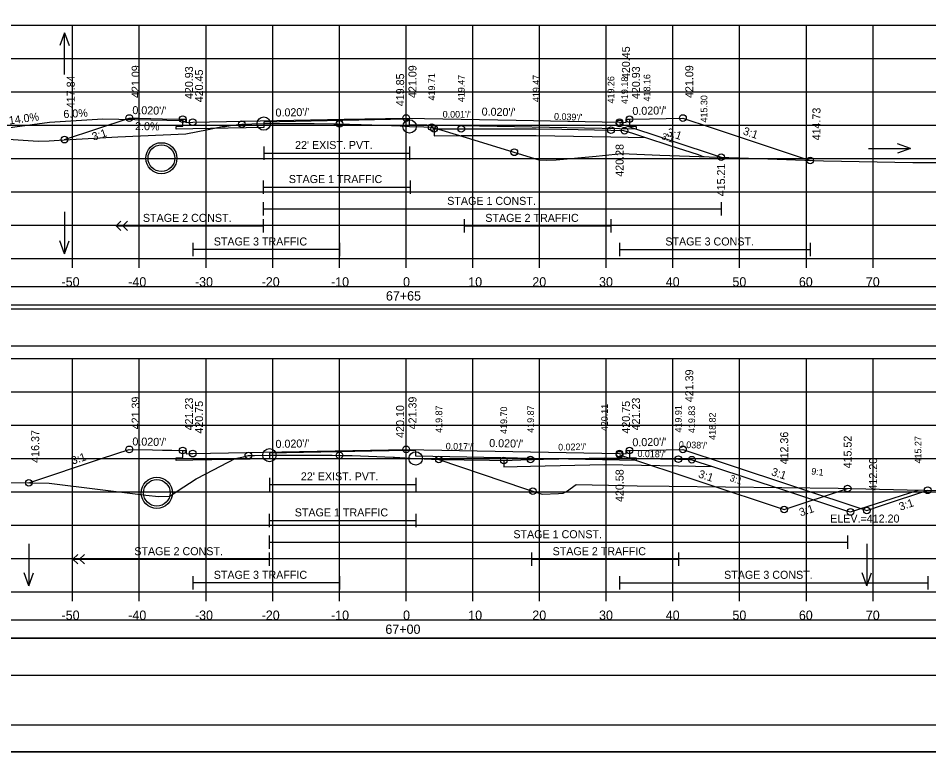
# Model space of a CAD drawing. Extents: x 1371057 to 1372761, y 380005 to 390517.
# Drawn here: x 1371502.7 to 1371639.2, y 385765.2 to 385875.2 of the extents above; entities that cross this region are included whole.
import ezdxf

# ---------------------------------------------------------------- set-up
doc = ezdxf.new("R2010")
doc.units = 0
for name, color, linetype in [('R_Alt Surface', 7, 'Continuous'), ('R_Axis', 7, 'Continuous'), ('R_Axis Annot', 7, 'Continuous'), ('R_Border', 7, 'Continuous'), ('R_Detour', 7, 'Continuous'), ('R_Draft', 7, 'Continuous'), ('R_Drive', 7, 'Continuous'), ('R_Exist Surface', 7, 'Continuous'), ('R_Fin Surface', 7, 'Continuous'), ('R_Fin Surface Annot', 7, 'Continuous'), ('R_Grid', 7, 'Continuous'), ('R_No Plot', 7, 'Continuous'), ('R_Striping', 7, 'Continuous'), ('R_Water', 7, 'Continuous'), ('R_Water Annot', 7, 'Continuous'), ('R_Xsect Elev', 7, 'Continuous'), ('R_Xsect Slope', 7, 'Continuous')]:
    doc.layers.add(name, color=color, linetype=linetype)

msp = doc.modelspace()

# ---------------------------------------------------------------- linework, layer by layer
at = {"layer": 'R_Alt Surface'}
for points in [[(1371594.37, 385860.11), (1371594.37, 385859.03), (1371595.37, 385859.01), (1371595.37, 385858.58), (1371592.87, 385858.63), (1371561.4, 385859.26), (1371561.39, 385860.09), (1371560.87, 385860.1), (1371539.53, 385859.67), (1371539.52, 385858.84), (1371528.87, 385858.63), (1371526.37, 385858.58), (1371526.37, 385859.01), (1371527.37, 385859.03), (1371527.37, 385860.11)], [(1371594.37, 385860.11), (1371594.37, 385859.03), (1371595.37, 385859.01), (1371595.37, 385858.58), (1371592.87, 385858.63), (1371561.4, 385859.26), (1371561.39, 385860.09), (1371560.87, 385860.1), (1371539.53, 385859.67), (1371539.52, 385858.84), (1371528.87, 385858.63), (1371526.37, 385858.58), (1371526.37, 385859.01), (1371527.37, 385859.03), (1371527.37, 385860.11)], [(1371539.53, 385856.02), (1371539.53, 385854.02)], [(1371561.39, 385856.02), (1371561.39, 385854.02)], [(1371539.53, 385855.02), (1371561.39, 385855.02)], [(1371594.37, 385810.41), (1371594.37, 385809.33), (1371595.37, 385809.31), (1371595.37, 385808.88), (1371592.87, 385808.93), (1371562.3, 385809.54), (1371562.3, 385810.37), (1371560.87, 385810.4), (1371540.38, 385809.99), (1371540.38, 385809.16), (1371528.87, 385808.93), (1371526.37, 385808.88), (1371526.37, 385809.31), (1371527.37, 385809.33), (1371527.37, 385810.41)], [(1371594.37, 385810.41), (1371594.37, 385809.33), (1371595.37, 385809.31), (1371595.37, 385808.88), (1371592.87, 385808.93), (1371562.3, 385809.54), (1371562.3, 385810.37), (1371560.87, 385810.4), (1371540.38, 385809.99), (1371540.38, 385809.16), (1371528.87, 385808.93), (1371526.37, 385808.88), (1371526.37, 385809.31), (1371527.37, 385809.33), (1371527.37, 385810.41)], [(1371540.38, 385806.32), (1371540.38, 385804.32)], [(1371562.3, 385806.32), (1371562.3, 385804.32)], [(1371540.38, 385805.32), (1371562.3, 385805.32)]]:
    msp.add_lwpolyline(points, dxfattribs=at)
at = {"layer": 'R_Axis'}
for p, q in [((1371410.87, 385839.19), (1371710.87, 385839.19)), ((1371510.87, 385837.79), (1371510.87, 385839.19)), ((1371520.87, 385837.79), (1371520.87, 385839.19)), ((1371530.87, 385837.79), (1371530.87, 385839.19)), ((1371540.87, 385837.79), (1371540.87, 385839.19)), ((1371550.87, 385837.79), (1371550.87, 385839.19)), ((1371560.87, 385837.79), (1371560.87, 385839.19)), ((1371570.87, 385837.79), (1371570.87, 385839.19)), ((1371580.87, 385837.79), (1371580.87, 385839.19)), ((1371590.87, 385837.79), (1371590.87, 385839.19)), ((1371600.87, 385837.79), (1371600.87, 385839.19)), ((1371610.87, 385837.79), (1371610.87, 385839.19)), ((1371620.87, 385837.79), (1371620.87, 385839.19)), ((1371630.87, 385837.79), (1371630.87, 385839.19)), ((1371410.87, 385789.19), (1371710.87, 385789.19)), ((1371510.87, 385787.79), (1371510.87, 385789.19)), ((1371520.87, 385787.79), (1371520.87, 385789.19)), ((1371530.87, 385787.79), (1371530.87, 385789.19)), ((1371540.87, 385787.79), (1371540.87, 385789.19)), ((1371550.87, 385787.79), (1371550.87, 385789.19)), ((1371560.87, 385787.79), (1371560.87, 385789.19)), ((1371570.87, 385787.79), (1371570.87, 385789.19)), ((1371580.87, 385787.79), (1371580.87, 385789.19)), ((1371590.87, 385787.79), (1371590.87, 385789.19)), ((1371600.87, 385787.79), (1371600.87, 385789.19)), ((1371610.87, 385787.79), (1371610.87, 385789.19)), ((1371620.87, 385787.79), (1371620.87, 385789.19)), ((1371630.87, 385787.79), (1371630.87, 385789.19))]:
    msp.add_line(p, q, dxfattribs=at)
at = {"layer": 'R_Border'}
msp.add_line((1371719.05, 385769.19), (1371402.87, 385769.19), dxfattribs=at)
at = {"layer": 'R_Detour'}
for points in [[(1371564.7, 385858.87), (1371565.06, 385858.66), (1371565.77, 385858.66), (1371568.32, 385858.65), (1371569.14, 385858.65), (1371573.54, 385858.65), (1371578.69, 385858.66), (1371580.36, 385858.66), (1371584.23, 385858.59), (1371591.58, 385858.45), (1371593.45, 385858.38), (1371593.62, 385858.37), (1371593.81, 385858.31), (1371594.82, 385857.98), (1371596.75, 385857.35), (1371600.42, 385856.15), (1371604.64, 385854.78), (1371605.26, 385854.57), (1371605.53, 385854.48)], [(1371565.06, 385858.66), (1371565.06, 385857.58), (1371569.14, 385857.65), (1371580.36, 385857.66), (1371591.58, 385857.45), (1371596.75, 385857.35)], [(1371565.78, 385809.05), (1371573.39, 385808.93), (1371575.51, 385808.89), (1371579.3, 385809.05), (1371579.53, 385809.06), (1371579.97, 385809.07), (1371581.45, 385809.1), (1371590.61, 385809.3), (1371593.68, 385809.24), (1371601.68, 385809.1), (1371603.1, 385809.04), (1371603.69, 385809.02), (1371604.76, 385808.67), (1371606.78, 385808), (1371612.39, 385806.15), (1371613.92, 385805.65), (1371617.28, 385804.54), (1371626.91, 385801.37), (1371627.48, 385801.18), (1371633.87, 385803.25), (1371637.62, 385804.46)], [(1371575.51, 385808.89), (1371575.51, 385807.97), (1371579.53, 385808.06), (1371590.61, 385808.3), (1371601.68, 385808.1), (1371606.78, 385808)]]:
    msp.add_lwpolyline(points, dxfattribs=at)
for points in [[(1371407.72, 385832.23), (1371714.03, 385832.23), (1371714.03, 385834.94), (1371407.72, 385834.94)], [(1371407.72, 385782.23), (1371714.03, 385782.23), (1371714.03, 385784.94), (1371407.72, 385784.94)]]:
    msp.add_lwpolyline(points, close=True, dxfattribs=at)
at = {"layer": 'R_Draft'}
for points in [[(1371407.64, 385826.09), (1371713.95, 385826.09), (1371713.95, 385831.61), (1371407.64, 385831.61)], [(1371407.72, 385776.71), (1371714.03, 385776.71), (1371714.03, 385782.23), (1371407.72, 385782.23)]]:
    msp.add_lwpolyline(points, close=True, dxfattribs=at)
at = {"layer": 'R_Drive'}
for p, q in [((1371507.39, 385859.62), (1371499.51, 385858.52)), ((1371515.38, 385860.1), (1371507.39, 385859.62)), ((1371527.38, 385859.86), (1371515.38, 385860.1)), ((1371527.88, 385859.61), (1371527.38, 385859.86))]:
    msp.add_line(p, q, dxfattribs=at)
at = {"layer": 'R_Exist Surface'}
for points in [[(1371497.47, 385857.33), (1371505.7, 385856.81), (1371507.34, 385856.84), (1371509.59, 385857.02), (1371517.67, 385857.44), (1371527.82, 385857.9), (1371531.18, 385858.55), (1371533.29, 385859), (1371533.74, 385858.99), (1371534.54, 385859.14), (1371535.84, 385859.3), (1371536.25, 385859.34), (1371537.72, 385859.38), (1371539.53, 385859.43), (1371539.6, 385859.43), (1371539.66, 385859.43), (1371542.97, 385859.44), (1371547.07, 385859.43), (1371550.01, 385859.41), (1371550.26, 385859.41), (1371550.26, 385859.41), (1371550.61, 385859.41), (1371554.12, 385859.29), (1371557.36, 385859.2), (1371559.98, 385859.08), (1371561.39, 385859.01), (1371563.54, 385858.94), (1371564.7, 385858.9), (1371569.86, 385857.37), (1371580.78, 385853.98), (1371581.86, 385853.97), (1371583.38, 385853.99), (1371589.37, 385854.56), (1371593.15, 385854.94), (1371598.89, 385854.72), (1371613.69, 385854.2), (1371623.42, 385853.84), (1371636.83, 385853.61), (1371647.72, 385853.61)], [(1371487.18, 385805.86), (1371507.36, 385805.5), (1371521.87, 385803.72), (1371523.81, 385803.5), (1371525.33, 385803.57), (1371525.46, 385803.57), (1371526.54, 385804.31), (1371529.38, 385806.14), (1371530.83, 385806.9), (1371535.24, 385809.18), (1371536.47, 385809.46), (1371537.22, 385809.66), (1371538.15, 385809.67), (1371540.38, 385809.7), (1371540.38, 385809.7), (1371540.38, 385809.7), (1371540.89, 385809.7), (1371540.95, 385809.7), (1371549.04, 385809.69), (1371549.76, 385809.69), (1371551.05, 385809.67), (1371551.16, 385809.67), (1371551.19, 385809.67), (1371552.3, 385809.65), (1371552.77, 385809.63), (1371558.91, 385809.39), (1371559.11, 385809.38), (1371562.28, 385809.21), (1371562.3, 385809.21), (1371562.49, 385809.2), (1371565.78, 385809.05), (1371578.61, 385804.72), (1371581.25, 385803.86), (1371583.7, 385803.96), (1371584.4, 385804), (1371584.89, 385804.27), (1371586.36, 385805.31), (1371593.61, 385805.15), (1371595.5, 385805.09), (1371600.3, 385805.03), (1371625.66, 385804.74), (1371635.97, 385804.49), (1371651.82, 385804.2)]]:
    msp.add_lwpolyline(points, dxfattribs=at)
at = {"layer": 'R_Fin Surface'}
for points in [[(1371509.64, 385857.03), (1371509.64, 385857.03), (1371519.37, 385860.27), (1371519.37, 385860.27), (1371520.86, 385860.24), (1371524.37, 385860.17), (1371526.97, 385860.12), (1371527.37, 385860.11), (1371527.87, 385860.11), (1371527.87, 385859.85), (1371527.88, 385859.61), (1371528.87, 385859.63), (1371551.57, 385860.08), (1371560.87, 385860.27), (1371560.87, 385860.27), (1371577.38, 385859.94), (1371592.87, 385859.63), (1371593.87, 385859.61), (1371593.87, 385859.88), (1371593.87, 385860.11), (1371594.37, 385860.11), (1371597.37, 385860.17), (1371602.37, 385860.27), (1371606.61, 385858.86), (1371621.44, 385853.91)], [(1371504.31, 385805.55), (1371504.32, 385805.55), (1371515.2, 385809.18), (1371519.37, 385810.57), (1371522.86, 385810.5), (1371524.37, 385810.47), (1371525.74, 385810.45), (1371527.37, 385810.41), (1371527.55, 385810.41), (1371527.87, 385810.41), (1371527.87, 385810.12), (1371527.88, 385809.91), (1371528.49, 385809.93), (1371528.87, 385809.93), (1371528.87, 385809.93), (1371560.87, 385810.57), (1371560.88, 385810.57), (1371592.87, 385809.93), (1371593.87, 385809.91), (1371593.87, 385810.41), (1371593.96, 385810.41), (1371594.37, 385810.41), (1371597.37, 385810.47), (1371602.37, 385810.57), (1371608.68, 385808.47), (1371629.92, 385801.39), (1371629.93, 385801.39), (1371632.3, 385802.18), (1371639.06, 385804.43)]]:
    msp.add_lwpolyline(points, dxfattribs=at)
at = {"layer": 'R_Grid'}
for p, q in [((1371410.87, 385874.19), (1371710.87, 385874.19)), ((1371510.87, 385839.19), (1371510.87, 385874.19)), ((1371520.87, 385839.19), (1371520.87, 385874.19)), ((1371530.87, 385839.19), (1371530.87, 385874.19)), ((1371540.87, 385839.19), (1371540.87, 385874.19)), ((1371550.87, 385839.19), (1371550.87, 385874.19)), ((1371560.87, 385839.19), (1371560.87, 385874.19)), ((1371570.87, 385839.19), (1371570.87, 385874.19)), ((1371580.87, 385839.19), (1371580.87, 385874.19)), ((1371590.87, 385839.19), (1371590.87, 385874.19)), ((1371600.87, 385839.19), (1371600.87, 385874.19)), ((1371610.87, 385839.19), (1371610.87, 385874.19)), ((1371620.87, 385839.19), (1371620.87, 385874.19)), ((1371630.87, 385839.19), (1371630.87, 385874.19)), ((1371410.87, 385869.19), (1371710.87, 385869.19)), ((1371410.87, 385864.19), (1371710.87, 385864.19)), ((1371410.87, 385859.19), (1371710.87, 385859.19)), ((1371410.87, 385854.19), (1371710.87, 385854.19)), ((1371410.87, 385849.19), (1371710.87, 385849.19)), ((1371410.87, 385844.19), (1371710.87, 385844.19)), ((1371410.87, 385839.19), (1371710.87, 385839.19)), ((1371410.87, 385824.19), (1371710.87, 385824.19)), ((1371510.87, 385789.19), (1371510.87, 385824.19)), ((1371520.87, 385789.19), (1371520.87, 385824.19)), ((1371530.87, 385789.19), (1371530.87, 385824.19)), ((1371540.87, 385789.19), (1371540.87, 385824.19)), ((1371550.87, 385789.19), (1371550.87, 385824.19)), ((1371560.87, 385789.19), (1371560.87, 385824.19)), ((1371570.87, 385789.19), (1371570.87, 385824.19)), ((1371580.87, 385789.19), (1371580.87, 385824.19)), ((1371590.87, 385789.19), (1371590.87, 385824.19)), ((1371600.87, 385789.19), (1371600.87, 385824.19)), ((1371610.87, 385789.19), (1371610.87, 385824.19)), ((1371620.87, 385789.19), (1371620.87, 385824.19)), ((1371630.87, 385789.19), (1371630.87, 385824.19)), ((1371410.87, 385819.19), (1371710.87, 385819.19)), ((1371410.87, 385814.19), (1371710.87, 385814.19)), ((1371410.87, 385809.19), (1371710.87, 385809.19)), ((1371410.87, 385804.19), (1371710.87, 385804.19)), ((1371410.87, 385799.19), (1371710.87, 385799.19)), ((1371410.87, 385794.19), (1371710.87, 385794.19)), ((1371410.87, 385789.19), (1371710.87, 385789.19))]:
    msp.add_line(p, q, dxfattribs=at)
at = {"layer": 'R_No Plot'}
msp.add_line((1371390.47, 385765.21), (1371723.8, 385765.21), dxfattribs=at)
for points in [[(1371390.46, 385978.54), (1371723.8, 385978.54), (1371723.8, 385765.2), (1371390.46, 385765.2)], [(1371636.79, 385974.65), (1371656.41, 385974.65), (1371656.41, 385964.77), (1371672.52, 385964.77), (1371695.72, 385964.77), (1371695.84, 385936.61), (1371719.05, 385936.61), (1371719.05, 385769.19), (1371402.87, 385769.19), (1371402.87, 385974.65)]]:
    msp.add_lwpolyline(points, close=True, dxfattribs=at)
for points in [[(1371592.87, 385859.46), (1371608.08, 385854.39)], [(1371592.87, 385809.77), (1371617.55, 385801.54), (1371627.06, 385804.71)]]:
    msp.add_lwpolyline(points, dxfattribs=at)
for centre, radius in [((1371519.37, 385860.27), 0.5), ((1371527.37, 385860.11), 0.5), ((1371560.87, 385860.27), 0.5), ((1371594.37, 385860.11), 0.5), ((1371602.37, 385860.27), 0.5), ((1371528.87, 385859.63), 0.5), ((1371536.25, 385859.34), 0.5), ((1371539.53, 385859.43), 1), ((1371550.87, 385859.4), 0.5), ((1371561.39, 385859.01), 1), ((1371564.7, 385858.9), 0.5), ((1371565.06, 385858.66), 0.5), ((1371569.14, 385858.65), 0.5), ((1371592.87, 385859.63), 0.5), ((1371592.87, 385859.46), 0.5), ((1371591.58, 385858.45), 0.5), ((1371593.62, 385858.37), 0.5), ((1371509.64, 385857.03), 0.5), ((1371524.18, 385854.24), 2.33), ((1371577.09, 385855.13), 0.5), ((1371608.08, 385854.39), 0.5), ((1371621.44, 385853.91), 0.5), ((1371519.37, 385810.57), 0.5), ((1371527.37, 385810.41), 0.5), ((1371528.87, 385809.93), 0.5), ((1371537.22, 385809.66), 0.5), ((1371540.38, 385809.7), 1), ((1371550.87, 385809.67), 0.5), ((1371560.87, 385810.57), 0.5), ((1371562.3, 385809.21), 1), ((1371592.87, 385809.93), 0.5), ((1371592.87, 385809.77), 0.5), ((1371594.37, 385810.41), 0.5), ((1371602.37, 385810.57), 0.5), ((1371565.78, 385809.05), 0.5), ((1371575.51, 385808.89), 0.5), ((1371579.53, 385809.06), 0.5), ((1371601.68, 385809.1), 0.5), ((1371603.69, 385809.02), 0.5), ((1371504.31, 385805.55), 0.5), ((1371523.5, 385804.05), 2.33), ((1371579.87, 385804.31), 0.5), ((1371627.06, 385804.71), 0.5), ((1371639.06, 385804.43), 0.5), ((1371617.55, 385801.54), 0.5), ((1371629.93, 385801.39), 0.5), ((1371627.48, 385801.18), 0.5)]:
    msp.add_circle(centre, radius, dxfattribs=at)
at = {"layer": 'R_Striping'}
for p, q in [((1371539.46, 385850.91), (1371539.46, 385848.91)), ((1371539.46, 385849.91), (1371561.46, 385849.91)), ((1371561.46, 385850.91), (1371561.46, 385848.91)), ((1371539.46, 385847.64), (1371539.46, 385845.64)), ((1371608.08, 385847.64), (1371608.08, 385845.64)), ((1371539.46, 385846.64), (1371608.08, 385846.64)), ((1371517.41, 385844.09), (1371518.12, 385844.8)), ((1371518.41, 385844.09), (1371519.12, 385844.8)), ((1371539.46, 385845.09), (1371539.46, 385843.09)), ((1371569.58, 385845.09), (1371569.58, 385843.09)), ((1371591.58, 385845.09), (1371591.58, 385843.09)), ((1371517.41, 385844.09), (1371539.46, 385844.09)), ((1371518.12, 385843.38), (1371517.41, 385844.09)), ((1371519.12, 385843.38), (1371518.41, 385844.09)), ((1371569.58, 385844.09), (1371591.58, 385844.09)), ((1371528.87, 385841.55), (1371528.87, 385839.55)), ((1371550.87, 385841.55), (1371550.87, 385839.55)), ((1371592.87, 385841.55), (1371592.87, 385839.55)), ((1371621.44, 385841.55), (1371621.44, 385839.55)), ((1371550.87, 385840.55), (1371528.87, 385840.55)), ((1371592.87, 385840.55), (1371621.44, 385840.55)), ((1371540.34, 385800.91), (1371540.34, 385798.91)), ((1371562.34, 385800.91), (1371562.34, 385798.91)), ((1371540.34, 385799.91), (1371562.34, 385799.91)), ((1371540.34, 385797.64), (1371540.34, 385795.64)), ((1371540.34, 385796.64), (1371627.06, 385796.64)), ((1371627.06, 385797.64), (1371627.06, 385795.64)), ((1371540.34, 385795.09), (1371540.34, 385793.09)), ((1371579.68, 385795.09), (1371579.68, 385793.09)), ((1371601.68, 385795.09), (1371601.68, 385793.09)), ((1371510.92, 385794.09), (1371511.63, 385794.8)), ((1371510.92, 385794.09), (1371540.34, 385794.09)), ((1371511.63, 385793.38), (1371510.92, 385794.09)), ((1371511.92, 385794.09), (1371512.63, 385794.8)), ((1371512.63, 385793.38), (1371511.92, 385794.09)), ((1371579.68, 385794.09), (1371601.68, 385794.09)), ((1371528.87, 385791.55), (1371528.87, 385789.55)), ((1371550.87, 385791.55), (1371550.87, 385789.55)), ((1371592.87, 385791.55), (1371592.87, 385789.55)), ((1371639.06, 385791.55), (1371639.06, 385789.55)), ((1371550.87, 385790.55), (1371528.87, 385790.55)), ((1371592.87, 385790.55), (1371639.06, 385790.55))]:
    msp.add_line(p, q, dxfattribs=at)
at = {"layer": 'R_Water'}
for centre in [(1371524.18, 385854.24), (1371523.5, 385804.05)]:
    msp.add_circle(centre, 2, dxfattribs=at)
at = {"layer": 'R_Water Annot'}
for p, q in [((1371509.64, 385873.07), (1371508.94, 385871.15)), ((1371509.64, 385866.79), (1371509.64, 385873.07)), ((1371509.64, 385873.07), (1371510.34, 385871.15)), ((1371630.18, 385855.68), (1371636.46, 385855.68)), ((1371636.46, 385855.68), (1371634.54, 385856.38)), ((1371636.46, 385855.68), (1371634.54, 385854.98)), ((1371509.64, 385846.2), (1371509.64, 385839.92)), ((1371509.64, 385839.92), (1371508.94, 385841.84)), ((1371509.64, 385839.92), (1371510.34, 385841.84)), ((1371504.32, 385796.4), (1371504.32, 385790.12)), ((1371629.92, 385796.4), (1371629.92, 385790.12)), ((1371504.32, 385790.12), (1371503.62, 385792.04)), ((1371504.32, 385790.12), (1371505.02, 385792.04)), ((1371629.92, 385790.12), (1371629.22, 385792.04)), ((1371629.92, 385790.12), (1371630.62, 385792.04))]:
    msp.add_line(p, q, dxfattribs=at)
at = {"layer": 'R_Xsect Elev'}
for p, q in [((1371560.87, 385859.04), (1371560.87, 385869.04)), ((1371560.87, 385809.29), (1371560.87, 385819.29))]:
    msp.add_line(p, q, dxfattribs=at)

# ---------------------------------------------------------------- texts
at = {"layer": 'R_Axis Annot'}
for s, p in [('-50', (1371509.21, 385834.99)), ('-40', (1371519.21, 385834.99)), ('-30', (1371529.21, 385834.99)), ('-20', (1371539.21, 385834.99)), ('-10', (1371549.61, 385834.99)), ('0', (1371560.41, 385834.99)), ('10', (1371570.18, 385834.99)), ('20', (1371579.79, 385834.99)), ('30', (1371589.79, 385834.99)), ('40', (1371599.79, 385834.99)), ('50', (1371609.79, 385834.99)), ('60', (1371619.75, 385834.99)), ('70', (1371629.79, 385834.99)), ('67+65', (1371557.84, 385832.89)), ('-50', (1371509.21, 385784.99)), ('-40', (1371519.21, 385784.99)), ('-30', (1371529.21, 385784.99)), ('-20', (1371539.21, 385784.99)), ('-10', (1371549.61, 385784.99)), ('0', (1371560.41, 385784.99)), ('10', (1371570.18, 385784.99)), ('20', (1371579.79, 385784.99)), ('30', (1371589.79, 385784.99)), ('40', (1371599.79, 385784.99)), ('50', (1371609.79, 385784.99)), ('60', (1371619.75, 385784.99)), ('70', (1371629.79, 385784.99)), ('67+00', (1371557.76, 385782.89))]:
    msp.add_text(s, height=1.4, dxfattribs=at).set_placement(p)
at = {"layer": 'R_Fin Surface Annot'}
for s, rotation, p in [('419.71', 90, (1371565.2, 385862.9)), ('419.47', 90, (1371569.64, 385862.65)), ('419.47', 90, (1371580.86, 385862.66)), ('419.26', 90, (1371592.08, 385862.45)), ('419.18', 90, (1371594.12, 385862.37)), ('418.16', 90, (1371597.47, 385862.76)), ('415.30', 90, (1371606.03, 385859.6)), ("0.001'/'", 0.0021, (1371566.35, 385860.33)), ("0.039'/'", 357.7939, (1371583.03, 385860.02)), ('3:1', 341.9323, (1371599.07, 385857.12)), ('419.87', 90, (1371566.28, 385813.05)), ('419.70', 90, (1371576.01, 385812.89)), ('419.87', 90, (1371580.03, 385813.06)), ('420.11', 90, (1371591.11, 385813.3)), ('419.91', 90, (1371602.18, 385813.1)), ('419.83', 90, (1371604.19, 385813.02)), ('418.82', 90, (1371607.28, 385812)), ("0.017'/'", 359.029, (1371566.8, 385810.55)), ("0.022'/'", 1.2423, (1371583.67, 385810.39)), ("0.038'/'", 357.8211, (1371601.74, 385810.81)), ('415.27', 90, (1371638.12, 385808.46)), ("0.018'/'", 358.9613, (1371595.54, 385809.42)), ('9:1', 353.4451, (1371621.56, 385806.81)), ('3:1', 341.7626, (1371609.3, 385805.87))]:
    msp.add_text(s, height=1, rotation=rotation, dxfattribs=at).set_placement(p)
at = {"layer": 'R_No Plot'}
for s, rotation, p in [('3:1', 341.5668, (1371599.85, 385857.67)), ('420.28', 90, (1371593.47, 385851.46)), ('415.21', 90, (1371608.68, 385848.52)), ('412.36', 90, (1371618.15, 385808.31)), ('415.52', 90, (1371627.66, 385807.71)), ('420.58', 90, (1371593.47, 385802.67)), ('3:1', 341.5668, (1371604.58, 385806.39)), ('3:1', 18.4332, (1371620.02, 385800.5))]:
    msp.add_text(s, height=1.2, rotation=rotation, dxfattribs=at).set_placement(p)
at = {"layer": 'R_Striping'}
for s, p in [('STAGE 1 TRAFFIC', (1371543.29, 385850.51)), ('STAGE 1 CONST.', (1371567.03, 385847.24)), ('STAGE 2 CONST.', (1371521.41, 385844.69)), ('STAGE 2 TRAFFIC', (1371572.74, 385844.69)), ('STAGE 3 TRAFFIC', (1371532.03, 385841.15)), ('STAGE 3 CONST.', (1371599.73, 385841.15)), ('STAGE 1 TRAFFIC', (1371544.17, 385800.51)), ('STAGE 1 CONST.', (1371576.95, 385797.24)), ('STAGE 2 CONST.', (1371520.12, 385794.69)), ('STAGE 2 TRAFFIC', (1371582.83, 385794.69)), ('STAGE 3 TRAFFIC', (1371532.03, 385791.15)), ('STAGE 3 CONST.', (1371608.54, 385791.15))]:
    msp.add_text(s, height=1.2, dxfattribs=at).set_placement(p)
at = {"layer": 'R_Water'}
for p in [(1371544.22, 385855.62), (1371545.09, 385805.92)]:
    msp.add_text("22' EXIST. PVT.", height=1.2, dxfattribs=at).set_placement(p)
at = {"layer": 'R_Xsect Elev'}
for s, rotation, p in [('420.45', 90, (1371594.42, 385866.11)), ('421.09', 90, (1371520.92, 385863.27)), ('420.93', 90, (1371528.92, 385863.11)), ('420.45', 90, (1371530.42, 385862.63)), ('421.09', 90, (1371562.42, 385863.27)), ('420.93', 90, (1371595.92, 385863.11)), ('421.09', 90, (1371603.92, 385863.27)), ('417.84', 90, (1371511.19, 385861.74)), ('419.85', 90, (1371560.57, 385862.04)), ('14.0%', 7.9696, (1371501.39, 385859.29)), ('6.0%', 3.4336, (1371509.52, 385860.25)), ('414.73', 90, (1371622.99, 385856.91)), ('2.0%', 358.8542, (1371520.23, 385858.47)), ('421.39', 90, (1371603.92, 385817.64)), ('421.39', 90, (1371520.92, 385813.57)), ('421.23', 90, (1371528.92, 385813.41)), ('421.39', 90, (1371562.42, 385813.57)), ('421.23', 90, (1371595.92, 385813.41)), ('420.75', 90, (1371530.42, 385812.93)), ('420.10', 90, (1371560.57, 385812.29)), ('420.75', 90, (1371594.42, 385812.93)), ('416.37', 90, (1371505.86, 385808.55)), ('412.20', 90, (1371631.48, 385804.39))]:
    msp.add_text(s, height=1.2, rotation=rotation, dxfattribs=at).set_placement(p)
msp.add_text('ELEV.=412.20', height=1.2, dxfattribs=at).set_placement((1371624.44, 385799.59))
at = {"layer": 'R_Xsect Slope'}
for s, rotation, p in [("0.020'/'", 358.8543, (1371519.82, 385860.86)), ("0.020'/'", 1.1457, (1371594.8, 385860.72)), ("0.020'/'", 1.1458, (1371541.3, 385860.48)), ("0.020'/'", 358.8542, (1371572.18, 385860.64)), ('3:1', 18.437, (1371514.01, 385856.85)), ('3:1', 341.5648, (1371611.28, 385857.83)), ("0.020'/'", 358.8543, (1371519.82, 385811.16)), ("0.020'/'", 1.1458, (1371541.3, 385810.78)), ("0.020'/'", 358.8543, (1371573.32, 385810.92)), ("0.020'/'", 1.1457, (1371594.8, 385811.02)), ('3:1', 18.4359, (1371510.89, 385808.27)), ('3:1', 341.5653, (1371615.52, 385806.72)), ('3:1', 18.4313, (1371634.97, 385801.36))]:
    msp.add_text(s, height=1.2, rotation=rotation, dxfattribs=at).set_placement(p)

doc.saveas('drawing.dxf')
